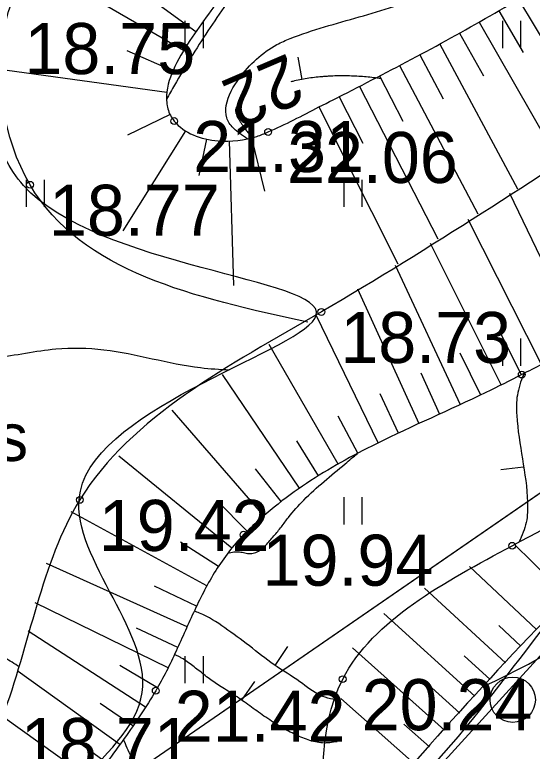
# Model space of a CAD drawing. Extents: x 521824 to 524158, y 294774 to 296228.
# Drawn here: x 522325.74 to 522337.15, y 295941 to 295957.24 of the extents above; entities that cross this region are included whole.
import ezdxf

# ---------------------------------------------------------------- set-up
doc = ezdxf.new("R2010")
doc.units = 0
for name, color, linetype in [('RAMI_UZMR_####_####_#', 7, 'Continuous'), ('RELJ_AATZ_####_TKST_#', 7, 'Continuous'), ('RELJ_ELEM_####_####_#', 7, 'Continuous'), ('RELJ_HORZ_####_TKST_#', 7, 'Continuous'), ('RELJ_HORZ_PAMT_####_#', 7, 'Continuous'), ('RELJ_HORZ_RESN_####_#', 7, 'Continuous'), ('RELJ_NOGA_####_####_#', 7, 'Continuous'), ('RELJ_NOGL_####_####_#', 7, 'Continuous'), ('ROBZ_IERR_####_####_#', 7, 'Continuous'), ('ROBZ_UZMR_####_####_#', 7, 'Continuous'), ('TERT_ELEM_####_####_#', 7, 'Continuous'), ('TERT_IZMT_####_TKST_#', 7, 'Continuous'), ('TERT_KONT_####_####_#', 7, 'Continuous')]:
    doc.layers.add(name, color=color, linetype=linetype)

msp = doc.modelspace()

# ---------------------------------------------------------------- linework, layer by layer
at = {"layer": 'RAMI_UZMR_####_####_#'}
msp.add_lwpolyline([(522238.336, 296053.36), (522285.71800000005, 296059.4810000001), (522293.25700000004, 296061.848), (522296.1550371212, 296062.19066618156), (522300.20081386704, 296058.47585271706), (522312.5079783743, 296044.5562533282), (522328.2404828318, 296022.8219247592), (522349.8543531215, 295994.6358569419), (522373.59202628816, 295961.69838929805), (522362.13780852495, 295957.1618769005), (522349.1742589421, 295950.88238868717), (522342.27800000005, 295948.544), (522332.7360928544, 295938.0710048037), (522327.68600000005, 295933.811), (522322.0216266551, 295927.6677244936), (522307.8129422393, 295919.9727079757), (522290.2123094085, 295909.1737619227), (522273.7068157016, 295894.679093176), (522210.195, 295852.81900000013)], dxfattribs=at)
at = {"layer": 'RELJ_ELEM_####_####_#'}
for centre in [(522329.25600000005, 295954.895), (522331.326, 295954.65400000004), (522326.07700000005, 295953.49), (522332.50100000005, 295950.686), (522336.91900000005, 295949.305), (522327.17500000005, 295946.543), (522330.787, 295945.776), (522336.70800000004, 295945.532), (522332.972, 295942.591), (522328.85000000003, 295942.336)]:
    msp.add_circle(centre, 0.075, dxfattribs=at)
at = {"layer": 'RELJ_HORZ_PAMT_####_#'}
for p, q in [((522336.45971249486, 295947.2102324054), (522336.9559387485, 295947.27154721)), ((522331.75605008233, 295943.311077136), (522331.4780701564, 295942.8954725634)), ((522331.0287734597, 295942.5383299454), (522330.74273815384, 295942.1282277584))]:
    msp.add_line(p, q, dxfattribs=at)
for points in [[(522353.67625367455, 295968.27993644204), (522353.66979644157, 295968.6073570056), (522353.74613474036, 295968.8305213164), (522353.9085824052, 295969.0512517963), (522354.02975658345, 295969.2697301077), (522354.0350589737, 295969.37818146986), (522353.9822744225, 295969.4861379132), (522353.7102964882, 295969.7698176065), (522353.4015245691, 295969.9861626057), (522353.0860289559, 295970.0863847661), (522352.79387994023, 295970.0216959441), (522352.2221755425, 295969.6350392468), (522352.0532030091, 295969.5101234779), (522351.12329243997, 295969.0942707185), (522350.6443529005, 295968.91670653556), (522350.17487502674, 295968.7185594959), (522349.24218005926, 295968.26723233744), (522344.62646006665, 295965.8194200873), (522344.4988132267, 295965.741969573), (522344.2350591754, 295965.5377309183), (522341.5613111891, 295963.5536913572), (522340.16628059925, 295962.65390913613), (522339.43707412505, 295962.25413264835), (522339.0624040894, 295962.0701549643), (522338.68020609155, 295961.89807266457), (522337.3891712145, 295961.45690672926), (522336.06272718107, 295961.1561031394), (522334.72473917, 295960.8997179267), (522334.0588740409, 295960.7581997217), (522333.3990723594, 295960.591807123), (522333.03206258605, 295960.49630118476), (522332.8514937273, 295960.4374366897), (522332.6756704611, 295960.3567941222), (522332.3934472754, 295960.1036586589), (522332.16127954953, 295959.7926823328), (522331.2556675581, 295958.6388714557), (522330.39981548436, 295957.4701135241), (522329.617628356, 295956.2851048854), (522329.26162946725, 295955.68609915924), (522329.08395636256, 295955.3738282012)], [(522330.86575076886, 295954.5008764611), (522330.70351586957, 295954.61810501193), (522330.627731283, 295954.6805707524), (522330.5562788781, 295954.74361488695), (522330.4674930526, 295954.8492655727), (522330.4147401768, 295954.9685548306), (522330.4055728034, 295955.238348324), (522330.69026827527, 295955.8348900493), (522331.5220729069, 295956.58106731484), (522331.81319373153, 295956.7125510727), (522333.33684370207, 295957.1891552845), (522334.8617812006, 295957.65221131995), (522336.3861524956, 295958.11291112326), (522337.9081038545, 295958.58244663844), (522338.26334781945, 295958.69522168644), (522338.67600000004, 295958.966)], [(522325.8442049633, 295942.86151185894), (522325.51940564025, 295943.0631522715), (522325.1785993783, 295943.26574624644), (522324.4891201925, 295943.648618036), (522323.0886789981, 295944.35185482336), (522321.67861085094, 295945.0227165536), (522320.28173592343, 295945.7223640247), (522319.63022702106, 295946.05285179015), (522319.3079188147, 295946.22938509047), (522319.1471637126, 295946.3238253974), (522318.9864983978, 295946.4236581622), (522318.84701906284, 295946.5459639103), (522318.7407638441, 295946.70080933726), (522318.66516109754, 295946.8714951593), (522318.61763917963, 295947.04132209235), (522318.6293477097, 295947.37772762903), (522318.6949589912, 295947.54439954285), (522318.80285195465, 295947.68894424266), (522318.95136727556, 295947.81224406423), (522319.1081543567, 295947.9133046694), (522319.41620409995, 295948.09363853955), (522319.56882603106, 295948.1695158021), (522319.7232513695, 295948.2405255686), (522320.04174449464, 295948.3547546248), (522321.3389811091, 295948.7064762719), (522322.6627581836, 295949.0636181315), (522323.98583491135, 295949.3897143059), (522324.6470242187, 295949.5379309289), (522325.31173792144, 295949.667231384), (522325.9792817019, 295949.778151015), (522326.64896124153, 295949.87122516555), (522327.7072025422, 295949.8525205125), (522328.7710600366, 295949.65601659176), (522329.83548504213, 295949.45857440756), (522330.4725159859, 295949.41046623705)], [(522336.98500067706, 295949.33826824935), (522336.95944477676, 295949.2992566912), (522336.87701704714, 295949.0766950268), (522336.822397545, 295948.8533743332), (522336.8080992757, 295948.40480347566), (522336.93430239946, 295947.4453660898), (522337.04720031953, 295946.4910595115), (522337.0178927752, 295946.047498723), (522336.95143926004, 295945.82856132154), (522336.8559392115, 295945.61199872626)], [(522336.0986938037, 295942.44754261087), (522336.10236046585, 295942.44895332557), (522336.1908645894, 295942.486893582), (522340.782, 295944.947), (522344.65911901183, 295945.9308435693)], [(522332.92891026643, 295942.11595623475), (522332.4814649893, 295942.23182288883), (522332.027824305, 295942.532590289), (522331.4598051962, 295942.9077006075), (522330.9129500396, 295943.3238829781), (522330.37005824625, 295943.7232420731), (522329.81392922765, 295944.0478825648), (522329.6978106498, 295944.09059500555)], [(522332.8469906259, 295941.2128312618), (522332.5288967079, 295941.1848604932), (522332.36795792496, 295941.207725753), (522332.2113722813, 295941.25070382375), (522332.0495478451, 295941.31205688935), (522331.8938049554, 295941.3849585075), (522331.73534710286, 295941.4683898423), (522331.57720754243, 295941.5579188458), (522331.2356195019, 295941.77880588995), (522330.9215306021, 295942.0026648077), (522330.6006826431, 295942.2262002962), (522330.2891376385, 295942.4250296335), (522330.0338368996, 295942.5981935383), (522329.7879526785, 295942.79008149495), (522329.5434388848, 295942.97353846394), (522329.4203982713, 295943.0548648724), (522329.3563996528, 295943.0902680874), (522329.2922494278, 295943.12140940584), (522329.2617309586, 295943.1334456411)], [(522326.6808122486, 295936.66422797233), (522326.6988722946, 295936.65110377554), (522326.77283580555, 295936.6086495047), (522326.9370839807, 295936.55443612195), (522327.1264620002, 295936.53574147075), (522327.22214690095, 295936.5416518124), (522327.3164630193, 295936.55731825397), (522327.5382967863, 295936.6164002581), (522327.7527660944, 295936.695233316), (522327.9608522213, 295936.7949153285), (522328.06280824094, 295936.85291778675), (522328.1635364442, 295936.9165441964), (522328.37122228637, 295937.063050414), (522328.56335559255, 295937.2184037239), (522328.7419216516, 295937.38675245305), (522328.90890575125, 295937.57224492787), (522329.04592309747, 295937.75269031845), (522329.1611546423, 295937.94572054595), (522329.24276822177, 295938.1323929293), (522329.27064705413, 295938.22427879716), (522329.2811294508, 295938.2696799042), (522329.2854782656, 295938.29222259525), (522329.28742606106, 295938.3034516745), (522329.28922144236, 295938.3146515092), (522329.3001567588, 295938.40579610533), (522329.30513017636, 295938.49685172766), (522329.2983665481, 295938.6787568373), (522329.2262240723, 295939.0421680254), (522329.1936630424, 295939.137021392), (522329.15940034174, 295939.2306837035), (522329.0854272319, 295939.4146603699), (522329.0036193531, 295939.59454844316), (522328.9132913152, 295939.7707983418), (522328.81080346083, 295939.9558115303), (522328.7066578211, 295940.13959239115), (522328.6027193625, 295940.3233574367), (522328.5008530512, 295940.5083231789), (522328.3043286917, 295940.882852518), (522328.13933916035, 295941.26252325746)]]:
    msp.add_spline(points, degree=3, dxfattribs=at)
at = {"layer": 'RELJ_HORZ_RESN_####_#'}
msp.add_line((522331.9806520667, 295956.3038520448), (522332.07245633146, 295955.81235232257), dxfattribs=at)
for points in [[(522333.81497532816, 295955.82955638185), (522333.65350574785, 295955.85033890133), (522333.49091617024, 295955.866995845), (522333.163563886, 295955.8872483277), (522332.99988416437, 295955.8910239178), (522332.8360615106, 295955.88915124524), (522332.67221778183, 295955.8821937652), (522332.59032609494, 295955.87698430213), (522332.5084748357, 295955.87071493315), (522332.18689793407, 295955.8320973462), (522331.8686979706, 295955.76900135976), (522331.82898629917, 295955.7593393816)], [(522330.7275946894, 295955.34146730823), (522330.6383232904, 295955.21411601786), (522330.6244769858, 295955.19028097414), (522330.6154179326, 295955.1655384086), (522330.6101426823, 295955.1137318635), (522330.61379471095, 295955.0856777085), (522330.61991501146, 295955.0578154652), (522330.64033132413, 295955.0036411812), (522330.7045868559, 295954.89026240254), (522330.7418952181, 295954.83434573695), (522330.7786069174, 295954.7800139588), (522330.8339420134, 295954.70087014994), (522330.8927158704, 295954.6243421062), (522330.9523675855, 295954.55322822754)], [(522330.4368125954, 295945.37192052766), (522330.5737182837, 295945.3972240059), (522330.6937427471, 295945.3976128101), (522330.81551681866, 295945.3754122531), (522330.9367405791, 295945.3611063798), (522331.05511410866, 295945.38517923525), (522331.2765531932, 295945.54479756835), (522331.4548038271, 295945.74848030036), (522331.6191315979, 295945.9490658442), (522331.7747131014, 295946.1553261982), (522332.11378887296, 295946.5395743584), (522333.0257089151, 295947.3372388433), (522333.2966954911, 295947.5679983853)]]:
    msp.add_spline(points, degree=3, dxfattribs=at)
at = {"layer": 'RELJ_NOGA_####_####_#'}
for p, q in [((522329.461331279, 295956.4461702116), (522326.5127891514, 295958.15811184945)), ((522336.84768584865, 295957.58034206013), (522338.6540336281, 295954.5412282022)), ((522329.7359171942, 295956.86374334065), (522328.9511755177, 295957.42337193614)), ((522336.41670312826, 295957.32686277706), (522336.9529698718, 295956.40725085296)), ((522335.9836749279, 295957.0768934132), (522337.7490866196, 295953.9775819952)), ((522335.5483216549, 295956.83099644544), (522336.0726855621, 295955.8901481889)), ((522335.11028993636, 295956.58990535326), (522336.8288701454, 295953.40266237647)), ((522329.2290383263, 295956.00363059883), (522328.220778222, 295956.4429258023)), ((522334.66933780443, 295956.35419674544), (522335.18287796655, 295955.3845922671)), ((522329.0958692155, 295955.52328996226), (522325.1595350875, 295956.06798416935)), ((522334.227202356, 295956.120710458), (522335.94836017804, 295952.85106892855)), ((522333.78430358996, 295955.8886760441), (522334.3003973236, 295954.8939072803)), ((522333.3402421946, 295955.65887418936), (522335.06909011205, 295952.2994562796)), ((522332.8949467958, 295955.4314724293), (522333.41543732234, 295954.40911153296)), ((522332.4486671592, 295955.2060101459), (522334.1849384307, 295951.74402274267)), ((522329.1656627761, 295955.0363620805), (522328.22570601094, 295954.57943772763)), ((522332.3225929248, 295955.14347124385), (522332.32303730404, 295955.1425754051)), ((522331.87418254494, 295954.9222757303), (522331.8743144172, 295954.9220062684)), ((522331.42507941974, 295954.70248859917), (522331.425518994, 295954.7015903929)), ((522329.5064291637, 295954.67926750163), (522328.12615273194, 295952.47614432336)), ((522329.9671894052, 295954.49158435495), (522329.79864112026, 295953.6970787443)), ((522330.4649189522, 295954.4597034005), (522330.56629965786, 295951.26883714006)), ((522330.9600219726, 295954.52191523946), (522331.2476579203, 295953.3452382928)), ((522338.25375684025, 295949.9720481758), (522336.6565062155, 295953.2946853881)), ((522337.3581662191, 295949.52723139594), (522335.74028418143, 295952.7206788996)), ((522336.4650216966, 295949.07746599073), (522334.90743078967, 295952.19796650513)), ((522335.5666160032, 295948.63838117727), (522334.13488390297, 295951.7125733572)), ((522334.6579214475, 295948.220931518), (522333.30302986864, 295951.18991737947)), ((522333.75161980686, 295947.79835779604), (522332.38958981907, 295950.61624837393)), ((522336.91202124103, 295949.30150015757), (522336.4366009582, 295950.2494981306)), ((522332.86803748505, 295947.33056999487), (522331.34720046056, 295949.9683540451)), ((522336.0174256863, 295948.8546275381), (522335.56054878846, 295949.7797961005)), ((522335.1127952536, 295948.4285123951), (522334.6980056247, 295949.33744456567)), ((522332.01914245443, 295946.8024011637), (522330.3208240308, 295949.31018459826)), ((522334.2035244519, 295948.0123127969), (522333.7990853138, 295948.88121894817)), ((522331.2290931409, 295946.190262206), (522329.2092620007, 295948.5195307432)), ((522333.3055183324, 295947.57260824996), (522332.8742790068, 295948.38839483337)), ((522332.4390574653, 295947.07375784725), (522331.95803788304, 295947.84528982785)), ((522330.5244968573, 295945.4823754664), (522328.03819275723, 295947.507639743)), ((522331.6153148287, 295946.5077217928), (522331.0504927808, 295947.2272358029)), ((522330.8618144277, 295945.8511057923), (522330.20505233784, 295946.5216784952)), ((522329.9776039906, 295944.64705436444), (522326.9853986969, 295946.2779464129)), ((522330.230669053, 295945.07817737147), (522329.3931915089, 295945.61451231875)), ((522337.93540738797, 295944.40445080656), (522336.75928786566, 295945.55973412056)), ((522329.5420576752, 295943.7472385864), (522326.441259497, 295945.1409892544)), ((522337.24266314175, 295943.6832828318), (522335.7688584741, 295945.0747781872)), ((522329.74996281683, 295944.20195493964), (522328.81912031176, 295944.6392637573)), ((522336.56046744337, 295942.95212332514), (522334.77218163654, 295944.5945868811)), ((522329.1207459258, 295942.84038820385), (522326.1876568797, 295944.2723702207)), ((522335.8864628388, 295942.2134010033), (522333.87515958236, 295944.0363776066)), ((522329.3356663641, 295943.29182809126), (522328.4254139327, 295943.7134926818)), ((522336.90039209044, 295943.3187978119), (522336.41092805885, 295943.7756087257)), ((522328.62240644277, 295941.97435837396), (522326.0375139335, 295943.64798141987)), ((522335.21831837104, 295941.4693717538), (522333.1896846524, 295943.2836115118)), ((522336.22266761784, 295942.5834899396), (522335.6476334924, 295943.1078164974)), ((522328.88723612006, 295942.39842494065), (522328.060353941, 295942.89165543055)), ((522328.05848677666, 295941.1486203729), (522325.8167736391, 295942.7608782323)), ((522335.5518135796, 295941.8419046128), (522334.9340894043, 295942.39682640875)), ((522328.3446742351, 295941.55860633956), (522327.6215592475, 295942.05540580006)), ((522334.5532252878, 295940.7226119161), (522332.9331680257, 295942.1628960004)), ((522327.4711376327, 295940.3392949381), (522325.4716323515, 295941.764988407)), ((522334.88552481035, 295941.0962119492), (522334.31959114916, 295941.6003217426)), ((522327.7646166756, 295940.74409818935), (522327.1358627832, 295941.20360891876))]:
    msp.add_line(p, q, dxfattribs=at)
for points in [[(522332.4486671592, 295955.2060101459), (522333.0684745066, 295955.51981650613), (522334.8140550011, 295956.43084458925), (522336.54160799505, 295957.3997003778), (522338.23000000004, 295958.439), (522340.2548588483, 295959.7885935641), (522342.2543094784, 295961.1599749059), (522344.2538553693, 295962.52161879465), (522346.27900000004, 295963.842), (522347.6916368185, 295964.6391543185), (522349.15018335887, 295965.3602490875), (522350.60388821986, 295966.09421931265), (522351.3130652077, 295966.4938249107), (522352.00200000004, 295966.93), (522352.7659264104, 295967.4968790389), (522353.4907546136, 295968.11182375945), (522354.19396732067, 295968.7495108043), (522354.8930472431, 295969.3846168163), (522355.2986227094, 295969.81848677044), (522355.49576936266, 295970.04013208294), (522355.705, 295970.239), (522356.65390699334, 295970.0598311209), (522357.6273617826, 295969.07019572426), (522358.5512718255, 295968.0585560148), (522359.4417847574, 295967.0192069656), (522360.3150482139, 295965.9464435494), (522361.9085947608, 295963.7687753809), (522361.99852902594, 295963.5924573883), (522362.0098792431, 295963.50814194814), (522361.96800000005, 295963.462), (522361.17901624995, 295963.30294057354), (522360.3411011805, 295963.1464154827), (522359.5012281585, 295963.0004625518), (522358.6654951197, 295962.8302634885), (522358.25108669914, 295962.7251909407), (522358.04508049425, 295962.66575728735), (522357.84, 295962.6010000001), (522355.9517139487, 295961.7318668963), (522354.2189477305, 295960.5683763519), (522352.54395764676, 295959.29519763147), (522351.6975837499, 295958.6751843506), (522350.829, 295958.097), (522347.59963820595, 295956.11506644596), (522344.375, 295954.124), (522343.3902816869, 295953.4089585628), (522342.458524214, 295952.6172405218), (522341.5217546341, 295951.8331522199), (522341.0333737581, 295951.4703149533), (522340.522, 295951.141), (522339.6365378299, 295950.6541907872), (522338.7323674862, 295950.20277703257), (522337.8222633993, 295949.7614747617), (522336.91900000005, 295949.305), (522336.1261569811, 295948.90832242), (522333.7138303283, 295947.78009221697), (522332.1761442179, 295946.90694321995), (522331.45806955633, 295946.38232077), (522331.11604228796, 295946.0904507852), (522330.94982091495, 295945.9361827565), (522330.787, 295945.776), (522330.17325521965, 295944.9864475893), (522329.7079475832, 295944.11252256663), (522329.29791615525, 295943.2103362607), (522329.084516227, 295942.7661799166), (522328.85000000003, 295942.336), (522328.15519607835, 295941.28509992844), (522327.4064026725, 295940.2477065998), (522326.7131579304, 295939.1952099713), (522326.42159697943, 295938.6543572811), (522326.2955722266, 295938.3787152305), (522326.23824757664, 295938.23939470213), (522326.185, 295938.099), (522326.2226791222, 295937.9369222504), (522326.44378055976, 295937.2985076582), (522326.680600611, 295936.66479406), (522326.9172124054, 295936.03216760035), (522327.1376890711, 295935.3970144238), (522327.155, 295935.066), (522326.9764115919, 295934.8641841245), (522326.790250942, 295934.6777435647), (522326.39788155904, 295934.345261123), (522325.5516309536, 295933.8018000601), (522324.2085347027, 295933.1185499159), (522323.76252632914, 295932.88016609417), (522323.556794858, 295932.8015035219), (522323.3341679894, 295932.74255061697), (522323.1385887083, 295932.6606139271), (522323.014, 295932.51300000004), (522321.346, 295928.151)], [(522335.34954582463, 295963.19032681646), (522335.1458622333, 295963.0100666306), (522333.96565347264, 295961.94652974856), (522332.79500000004, 295960.861), (522332.0287090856, 295960.045612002), (522331.34465398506, 295959.16212268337), (522330.7029869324, 295958.24427528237), (522330.06386016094, 295957.3258130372), (522329.65270784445, 295956.74631680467), (522329.27349509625, 295956.098294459), (522329.08749984, 295955.4563281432), (522329.1173581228, 295955.1609229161), (522329.1718211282, 295955.0236934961), (522329.25600000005, 295954.895), (522329.67621492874, 295954.5882351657), (522330.22404773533, 295954.4605264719), (522331.07914539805, 295954.5564169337), (522331.326, 295954.65400000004), (522332.4486671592, 295955.2060101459)], [(522342.27800000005, 295948.544), (522337.933, 295944.402), (522332.60500000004, 295938.54500000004)]]:
    msp.add_spline(points, degree=3, dxfattribs=at)
at = {"layer": 'RELJ_NOGL_####_####_#'}
for points in [[(522357.109, 295966.399), (522352.01800000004, 295962.771), (522339.462, 295955.043), (522332.50100000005, 295950.686), (522327.17500000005, 295946.543), (522325.45800000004, 295941.734), (522322.402, 295935.7260000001), (522321.346, 295928.151)], [(522332.2038521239, 295950.45862819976), (522326.07700000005, 295953.49), (522325.536, 295957.055), (522331.72400000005, 295963.14), (522333.82700000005, 295966.228)], [(522332.60500000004, 295938.54500000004), (522332.972, 295942.591), (522336.70800000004, 295945.532), (522342.27800000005, 295948.544)]]:
    msp.add_spline(points, degree=3, dxfattribs=at)
at = {"layer": 'ROBZ_IERR_####_####_#'}
msp.add_lwpolyline([(521982.72142177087, 296071.9435568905), (522030.7829999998, 296022.79399999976), (522033.55399999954, 296023.53500000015), (522231.7470000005, 296043.14800000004), (522293.95000000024, 296059.25), (522300.4160000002, 296060.9240000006), (522337.1440000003, 296010.44299999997), (522362.11199999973, 295976.4340000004), (522359.108, 295971.28500000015), (522349.7560000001, 295955.2589999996), (522172.84800000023, 295833.3920000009), (522168.0970000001, 295830.30399999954), (522159.466, 295824.6950000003), (522157.57199999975, 295823.4639999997), (522100.0300000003, 295786.06900000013), (522037.6330000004, 295748.40699999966), (521945.6600000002, 295684.5130000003), (521914.93752583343, 295661.4435568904)], dxfattribs=at)
at = {"layer": 'ROBZ_UZMR_####_####_#'}
msp.add_lwpolyline([(522223.09599999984, 295760.6429999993), (522168.0970000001, 295830.30399999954), (522172.84800000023, 295833.3920000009), (522349.7560000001, 295955.2589999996)], dxfattribs=at)
at = {"layer": 'TERT_ELEM_####_####_#'}
for p, q in [((522329.5, 295956.5), (522329.5, 295957.10000000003)), ((522329.9, 295956.5), (522329.9, 295957.10000000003)), ((522336.5, 295956.5), (522336.5, 295957.10000000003)), ((522336.9, 295956.5), (522336.9, 295957.10000000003)), ((522326, 295953), (522326, 295953.60000000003)), ((522326.4, 295953), (522326.4, 295953.60000000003)), ((522333, 295953), (522333, 295953.60000000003)), ((522333.4, 295953), (522333.4, 295953.60000000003)), ((522336.5, 295949.5), (522336.5, 295950.10000000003)), ((522336.9, 295949.5), (522336.9, 295950.10000000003)), ((522333, 295946), (522333, 295946.60000000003)), ((522333.4, 295946), (522333.4, 295946.60000000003)), ((522329.5, 295942.5), (522329.5, 295943.10000000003)), ((522329.9, 295942.5), (522329.9, 295943.10000000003))]:
    msp.add_line(p, q, dxfattribs=at)
msp.add_circle((522336.72017507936, 295942.13780971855), 0.5, dxfattribs=at)
at = {"layer": 'TERT_KONT_####_####_#'}
for points in [[(522314.2117442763, 295942.6109617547), (522314.67100000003, 295939.81200000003), (522313.87352353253, 295936.8931181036), (522312.337652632, 295932.32485283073), (522308.34805481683, 295929.95488679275), (522304.27951840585, 295926.1809969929), (522302.411, 295925.255), (522307.4619954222, 295923.7815970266), (522312.08462600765, 295928.80464648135), (522314.54097435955, 295929.3963256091), (522319.97678228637, 295926.43792997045), (522321.346, 295928.151), (522321.9782513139, 295932.85537281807), (522327.0281760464, 295934.91655056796), (522325.7537497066, 295938.0211867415), (522328.55125755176, 295942.29948197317), (522327.18661957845, 295946.7370754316), (522332.38958981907, 295950.61624837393), (522325.9357014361, 295953.47311473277), (522325.2809257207, 295954.7595424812), (522325.2809257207, 295957.1369739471), (522328.1805954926, 295959.57569740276), (522333.82700000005, 295966.228), (522333.55670592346, 295966.7233667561), (522333.3687024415, 295967.28652004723), (522333.375, 295967.807), (522331.7904727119, 295967.14817304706), (522324.152, 295963.653), (522324.152, 295968.10579470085), (522317.474946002, 295968.74298760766), (522318.5666563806, 295966.2852435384), (522317.9753132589, 295962.1890034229), (522316.612, 295959.369), (522316.0420761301, 295958.4113597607), (522313.66526228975, 295958.6325544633)], [(522331.6358174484, 295928.76207735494), (522327.84582384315, 295932.4392940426), (522327.68600000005, 295933.811), (522332.60500000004, 295938.54500000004), (522337.933, 295944.402), (522342.27800000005, 295948.544), (522349.58800000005, 295951.842), (522356.276, 295957.021), (522364.53900000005, 295962.024), (522368.31600000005, 295964.419)]]:
    msp.add_spline(points, degree=3, dxfattribs=at)

# ---------------------------------------------------------------- texts
at = {"layer": 'RELJ_AATZ_####_TKST_#'}
for s, p in [(' 18.75', (522325.536, 295955.93)), (' 21.31', (522329.25600000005, 295953.77)), (' 22.06', (522331.326, 295953.52900000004)), (' 18.77', (522326.07700000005, 295952.365)), (' 18.73', (522332.50100000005, 295949.561)), (' 19.42', (522327.17500000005, 295945.418)), (' 19.94', (522330.787, 295944.651)), (' 20.24', (522332.972, 295941.466)), (' 21.42', (522328.85000000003, 295941.211)), (' 18.71', (522325.45800000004, 295940.609))]:
    msp.add_text(s, height=1.125, dxfattribs=at).set_placement(p)
at = {"layer": 'RELJ_HORZ_####_TKST_#'}
msp.add_text('22', height=1.1249999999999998, rotation=203.21037695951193, dxfattribs=at).set_placement((522331.77141053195, 295956.40110688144))
at = {"layer": 'TERT_IZMT_####_TKST_#'}
msp.add_text('smilts', height=1.0499999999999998, dxfattribs=at).set_placement((522322.44692123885, 295947.40112290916))

doc.saveas('drawing.dxf')
